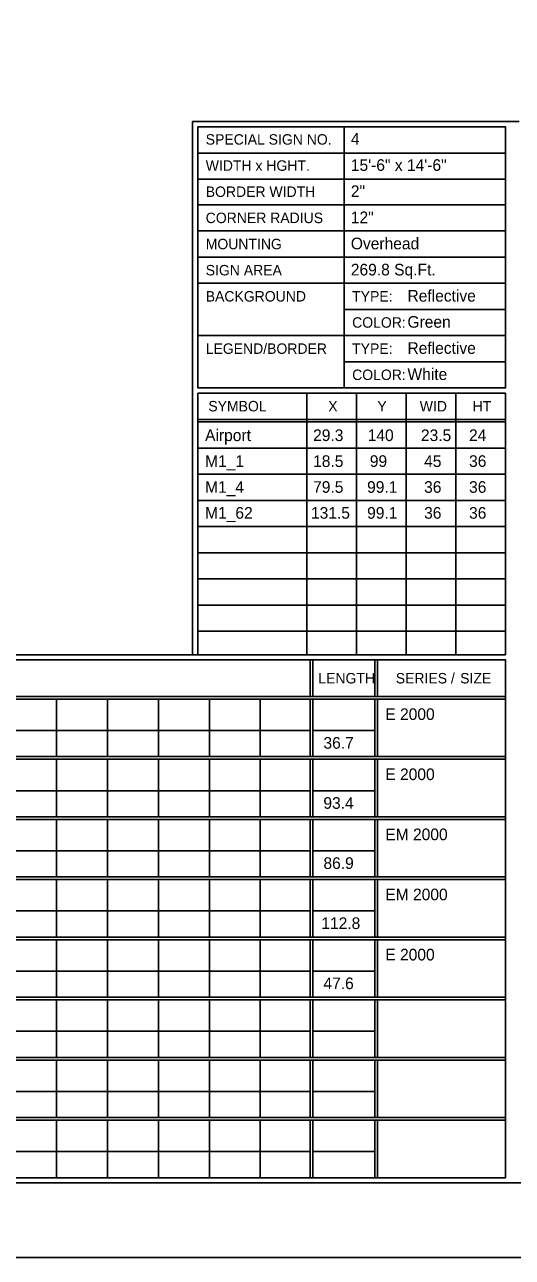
# Model space of a CAD drawing. Extents: x 2149961 to 2150220, y 145114 to 145240.
# Drawn here: x 2150113.5 to 2150135.1, y 145114.1 to 145168.7 of the extents above; entities that cross this region are included whole.
import ezdxf

# ---------------------------------------------------------------- set-up
doc = ezdxf.new("R2010")
doc.units = 0
for name, color, linetype in [('BORDER', 7, 'Continuous'), ('GSSHT', 7, 'Continuous'), ('Level 1', 7, 'Continuous'), ('PDF', 7, 'Continuous')]:
    doc.layers.add(name, color=color, linetype=linetype)

msp = doc.modelspace()

# ---------------------------------------------------------------- linework, layer by layer
at = {"layer": 'BORDER'}
for p, q in [((2150017.557, 145117.388), (2150171.536, 145117.388)), ((2150010.458, 145114.088), (2150174.061, 145114.088))]:
    msp.add_line(p, q, dxfattribs=at)
at = {"layer": 'Level 1'}
for p, q in [((2150120.969, 145164.445), (2150135.447, 145164.445)), ((2150127.694, 145164.213), (2150127.694, 145152.642)), ((2150121.201, 145163.054), (2150134.843, 145163.054)), ((2150121.201, 145161.894), (2150134.843, 145161.894)), ((2150121.201, 145160.758), (2150134.843, 145160.758)), ((2150121.201, 145159.598), (2150134.843, 145159.598)), ((2150121.201, 145158.439), (2150134.843, 145158.439)), ((2150121.201, 145157.28), (2150134.843, 145157.28)), ((2150127.694, 145156.12), (2150134.843, 145156.12)), ((2150121.201, 145154.961), (2150134.843, 145154.961)), ((2150127.694, 145153.801), (2150134.843, 145153.801)), ((2150121.201, 145140.809), (2150121.201, 145152.41)), ((2150121.201, 145152.41), (2150134.843, 145152.41)), ((2150126.031, 145152.404), (2150126.031, 145151.245)), ((2150128.234, 145152.404), (2150128.234, 145151.245)), ((2150130.437, 145152.404), (2150130.437, 145151.245)), ((2150132.64, 145152.404), (2150132.64, 145151.245)), ((2150134.843, 145152.41), (2150134.843, 145140.809)), ((2150121.201, 145151.245), (2150134.843, 145151.245)), ((2150121.201, 145151.129), (2150134.843, 145151.129)), ((2150126.031, 145151.245), (2150126.031, 145140.809)), ((2150128.234, 145151.245), (2150128.234, 145140.809)), ((2150130.437, 145151.245), (2150130.437, 145140.809)), ((2150132.64, 145151.245), (2150132.64, 145140.809)), ((2150121.201, 145149.969), (2150134.843, 145149.969)), ((2150121.201, 145148.81), (2150134.843, 145148.81)), ((2150121.201, 145147.65), (2150134.843, 145147.65)), ((2150121.201, 145146.491), (2150134.843, 145146.491)), ((2150121.201, 145145.331), (2150134.843, 145145.331)), ((2150121.201, 145144.172), (2150134.843, 145144.172)), ((2150121.201, 145143.012), (2150134.843, 145143.012)), ((2150121.201, 145141.853), (2150134.843, 145141.853)), ((2150076.316, 145140.809), (2150121.342, 145140.809)), ((2150134.843, 145140.809), (2150121.201, 145140.809)), ((2150126.185, 145140.578), (2150126.185, 145138.954)), ((2150126.301, 145140.578), (2150126.301, 145138.954)), ((2150129.048, 145140.578), (2150129.048, 145138.954)), ((2150129.164, 145140.578), (2150129.164, 145138.954)), ((2150076.548, 145138.954), (2150134.843, 145138.954)), ((2150076.548, 145138.838), (2150134.843, 145138.838)), ((2150114.927, 145138.838), (2150114.927, 145136.288)), ((2150117.199, 145138.838), (2150117.199, 145136.288)), ((2150119.449, 145138.838), (2150119.449, 145136.288)), ((2150121.721, 145138.838), (2150121.721, 145136.288)), ((2150123.97, 145138.838), (2150123.97, 145136.288)), ((2150126.185, 145138.838), (2150126.185, 145136.288)), ((2150126.301, 145138.838), (2150126.301, 145136.288)), ((2150129.048, 145138.838), (2150129.048, 145136.288)), ((2150129.164, 145138.838), (2150129.164, 145136.288)), ((2150076.548, 145137.447), (2150126.185, 145137.447)), ((2150126.301, 145137.447), (2150129.048, 145137.447)), ((2150076.548, 145136.288), (2150134.843, 145136.288)), ((2150076.548, 145136.172), (2150134.843, 145136.172)), ((2150114.927, 145136.172), (2150114.927, 145133.621)), ((2150117.199, 145136.172), (2150117.199, 145133.621)), ((2150119.449, 145136.172), (2150119.449, 145133.621)), ((2150121.721, 145136.172), (2150121.721, 145133.621)), ((2150123.97, 145136.172), (2150123.97, 145133.621)), ((2150126.185, 145136.172), (2150126.185, 145133.621)), ((2150126.301, 145136.172), (2150126.301, 145133.621)), ((2150129.048, 145136.172), (2150129.048, 145133.621)), ((2150129.164, 145136.172), (2150129.164, 145133.621)), ((2150076.548, 145134.78), (2150126.185, 145134.78)), ((2150126.301, 145134.78), (2150129.048, 145134.78)), ((2150076.548, 145133.621), (2150134.843, 145133.621)), ((2150076.548, 145133.505), (2150134.843, 145133.505)), ((2150114.927, 145133.505), (2150114.927, 145130.954)), ((2150117.199, 145133.505), (2150117.199, 145130.954)), ((2150119.449, 145133.505), (2150119.449, 145130.954)), ((2150121.721, 145133.505), (2150121.721, 145130.954)), ((2150123.97, 145133.505), (2150123.97, 145130.954)), ((2150126.185, 145133.505), (2150126.185, 145130.954)), ((2150126.301, 145133.505), (2150126.301, 145130.954)), ((2150129.048, 145133.505), (2150129.048, 145130.954)), ((2150129.164, 145133.505), (2150129.164, 145130.954)), ((2150076.548, 145132.113), (2150126.185, 145132.113)), ((2150126.301, 145132.113), (2150129.048, 145132.113)), ((2150076.548, 145130.954), (2150134.843, 145130.954)), ((2150076.548, 145130.838), (2150134.843, 145130.838)), ((2150114.927, 145130.838), (2150114.927, 145128.287)), ((2150117.199, 145130.838), (2150117.199, 145128.287)), ((2150119.449, 145130.838), (2150119.449, 145128.287)), ((2150121.721, 145130.838), (2150121.721, 145128.287)), ((2150123.97, 145130.838), (2150123.97, 145128.287)), ((2150126.185, 145130.838), (2150126.185, 145128.287)), ((2150126.301, 145130.838), (2150126.301, 145128.287)), ((2150129.048, 145130.838), (2150129.048, 145128.287)), ((2150129.164, 145130.838), (2150129.164, 145128.287)), ((2150076.548, 145129.447), (2150126.185, 145129.447)), ((2150126.301, 145129.447), (2150129.048, 145129.447)), ((2150076.548, 145128.287), (2150134.843, 145128.287)), ((2150076.548, 145128.171), (2150134.843, 145128.171)), ((2150114.927, 145128.171), (2150114.927, 145125.62)), ((2150117.199, 145128.171), (2150117.199, 145125.62)), ((2150119.449, 145128.171), (2150119.449, 145125.62)), ((2150121.721, 145128.171), (2150121.721, 145125.62)), ((2150123.97, 145128.171), (2150123.97, 145125.62)), ((2150126.185, 145128.171), (2150126.185, 145125.62)), ((2150126.301, 145128.171), (2150126.301, 145125.62)), ((2150129.048, 145128.171), (2150129.048, 145125.62)), ((2150129.164, 145128.171), (2150129.164, 145125.62)), ((2150076.548, 145126.78), (2150126.185, 145126.78)), ((2150126.301, 145126.78), (2150129.048, 145126.78)), ((2150076.548, 145125.62), (2150134.843, 145125.62)), ((2150076.548, 145125.504), (2150134.843, 145125.504)), ((2150114.927, 145125.504), (2150114.927, 145122.954)), ((2150117.199, 145125.504), (2150117.199, 145122.954)), ((2150119.449, 145125.504), (2150119.449, 145122.954)), ((2150121.721, 145125.504), (2150121.721, 145122.954)), ((2150123.97, 145125.504), (2150123.97, 145122.954)), ((2150126.185, 145125.504), (2150126.185, 145122.954)), ((2150126.301, 145125.504), (2150126.301, 145122.954)), ((2150129.048, 145125.504), (2150129.048, 145122.954)), ((2150129.164, 145125.504), (2150129.164, 145122.954)), ((2150076.548, 145124.113), (2150126.185, 145124.113)), ((2150126.301, 145124.113), (2150129.048, 145124.113)), ((2150076.548, 145122.954), (2150134.843, 145122.954)), ((2150076.548, 145122.838), (2150134.843, 145122.838)), ((2150114.927, 145122.838), (2150114.927, 145120.287)), ((2150117.199, 145122.838), (2150117.199, 145120.287)), ((2150119.449, 145122.838), (2150119.449, 145120.287)), ((2150121.721, 145122.838), (2150121.721, 145120.287)), ((2150123.97, 145122.838), (2150123.97, 145120.287)), ((2150126.185, 145122.838), (2150126.185, 145120.287)), ((2150126.301, 145122.838), (2150126.301, 145120.287)), ((2150129.048, 145122.838), (2150129.048, 145120.287)), ((2150129.164, 145122.838), (2150129.164, 145120.287)), ((2150076.548, 145121.446), (2150126.185, 145121.446)), ((2150126.301, 145121.446), (2150129.048, 145121.446)), ((2150076.548, 145120.287), (2150134.843, 145120.287)), ((2150076.548, 145120.171), (2150134.843, 145120.171)), ((2150114.927, 145120.171), (2150114.927, 145117.62)), ((2150117.199, 145120.171), (2150117.199, 145117.62)), ((2150119.449, 145120.171), (2150119.449, 145117.62)), ((2150121.721, 145120.171), (2150121.721, 145117.62)), ((2150123.97, 145120.171), (2150123.97, 145117.62)), ((2150126.185, 145120.171), (2150126.185, 145117.62)), ((2150126.301, 145120.171), (2150126.301, 145117.62)), ((2150129.048, 145120.171), (2150129.048, 145117.62)), ((2150129.164, 145120.171), (2150129.164, 145117.62)), ((2150076.548, 145118.779), (2150126.185, 145118.779)), ((2150126.301, 145118.779), (2150129.048, 145118.779))]:
    msp.add_line(p, q, dxfattribs=at)
msp.add_lwpolyline([(2150120.969, 145140.809), (2150120.969, 145164.445)], dxfattribs=at)
for points in [[(2150121.201, 145164.213), (2150134.843, 145164.213), (2150134.843, 145152.642), (2150121.201, 145152.642)], [(2150076.548, 145140.578), (2150134.843, 145140.578), (2150134.843, 145117.62), (2150076.548, 145117.62)]]:
    msp.add_lwpolyline(points, close=True, dxfattribs=at)
at = {"layer": 'PDF'}
msp.add_lwpolyline([(2150010.458, 145114.088), (2150174.061, 145114.088), (2150174.061, 145219.948), (2150010.458, 145219.948)], close=True, dxfattribs=at)

# ---------------------------------------------------------------- texts
at = {"layer": 'GSSHT'}
for s, height, p in [('4', 0.517, (2150127.983, 145163.42)), ('Overhead', 0.5165, (2150127.983, 145158.784))]:
    msp.add_text(s, height=height, dxfattribs=at).set_placement(p)
at = {"layer": 'Level 1'}
for s, height, p in [('SPECIAL SIGN NO.', 0.46374, (2150121.549, 145163.425)), ('WIDTH x HGHT.', 0.46374, (2150121.549, 145162.265)), ('15\'-6" x 14\'-6"', 0.51652, (2150127.983, 145162.261)), ('BORDER WIDTH', 0.46374, (2150121.549, 145161.106)), ('2"', 0.5165, (2150127.983, 145161.102)), ('CORNER RADIUS', 0.46374, (2150121.549, 145159.946)), ('12"', 0.5165, (2150127.983, 145159.943)), ('MOUNTING', 0.4637, (2150121.549, 145158.787)), ('SIGN AREA', 0.4638, (2150121.549, 145157.627)), ('269.8 Sq.Ft.', 0.51652, (2150127.983, 145157.625)), ('BACKGROUND', 0.4637, (2150121.549, 145156.468)), ('TYPE:', 0.4637, (2150128.042, 145156.468)), ('Reflective', 0.5165, (2150130.494, 145156.466)), ('COLOR:', 0.4637, (2150128.042, 145155.308)), ('Green', 0.5165, (2150130.494, 145155.308)), ('LEGEND/BORDER', 0.46374, (2150121.549, 145154.149)), ('TYPE:', 0.4637, (2150128.042, 145154.149)), ('Reflective', 0.5165, (2150130.494, 145154.149)), ('COLOR:', 0.4637, (2150128.042, 145152.989)), ('White', 0.5165, (2150130.494, 145152.99)), ('SYMBOL', 0.4637, (2150121.665, 145151.598)), ('X', 0.464, (2150126.981, 145151.593)), ('Y', 0.464, (2150129.161, 145151.593)), ('WID', 0.4637, (2150131.04, 145151.593)), ('HT', 0.4637, (2150133.382, 145151.593)), ('Airport', 0.5165, (2150121.52, 145150.282)), ('29.3', 0.5165, (2150126.31, 145150.282)), ('140', 0.5165, (2150128.73, 145150.282)), ('23.5', 0.5165, (2150131.092, 145150.282)), ('24', 0.5165, (2150133.223, 145150.282)), ('M1_1', 0.5165, (2150121.52, 145149.135)), ('18.5', 0.5165, (2150126.31, 145149.135)), ('99', 0.5165, (2150128.824, 145149.135)), ('45', 0.5165, (2150131.233, 145149.135)), ('36', 0.5165, (2150133.225, 145149.135)), ('M1_4', 0.5165, (2150121.52, 145147.987)), ('79.5', 0.5165, (2150126.31, 145147.987)), ('99.1', 0.5165, (2150128.704, 145147.987)), ('36', 0.5165, (2150131.233, 145147.987)), ('36', 0.5165, (2150133.225, 145147.987)), ('M1_62', 0.5165, (2150121.52, 145146.839)), ('131.5', 0.5165, (2150126.216, 145146.839)), ('99.1', 0.5165, (2150128.704, 145146.839)), ('36', 0.5165, (2150131.233, 145146.839)), ('36', 0.5165, (2150133.225, 145146.839)), ('LENGTH', 0.4638, (2150126.541, 145139.534)), ('LENGTH', 0.4638, (2150126.541, 145139.534)), ('SERIES /', 0.4638, (2150129.975, 145139.534)), ('SIZE', 0.4638, (2150132.832, 145139.534)), ('E 2000', 0.5165, (2150129.512, 145137.915)), ('36.7', 0.5165, (2150126.768, 145136.64)), ('E 2000', 0.5165, (2150129.512, 145135.25)), ('93.4', 0.5165, (2150126.766, 145133.975)), ('EM 2000', 0.5165, (2150129.512, 145132.584)), ('86.9', 0.5165, (2150126.768, 145131.309)), ('EM 2000', 0.5165, (2150129.512, 145129.919)), ('112.8', 0.5165, (2150126.674, 145128.644)), ('E 2000', 0.5165, (2150129.512, 145127.253)), ('47.6', 0.5165, (2150126.768, 145125.979))]:
    msp.add_text(s, height=height, dxfattribs=at).set_placement(p)

doc.saveas('drawing.dxf')
